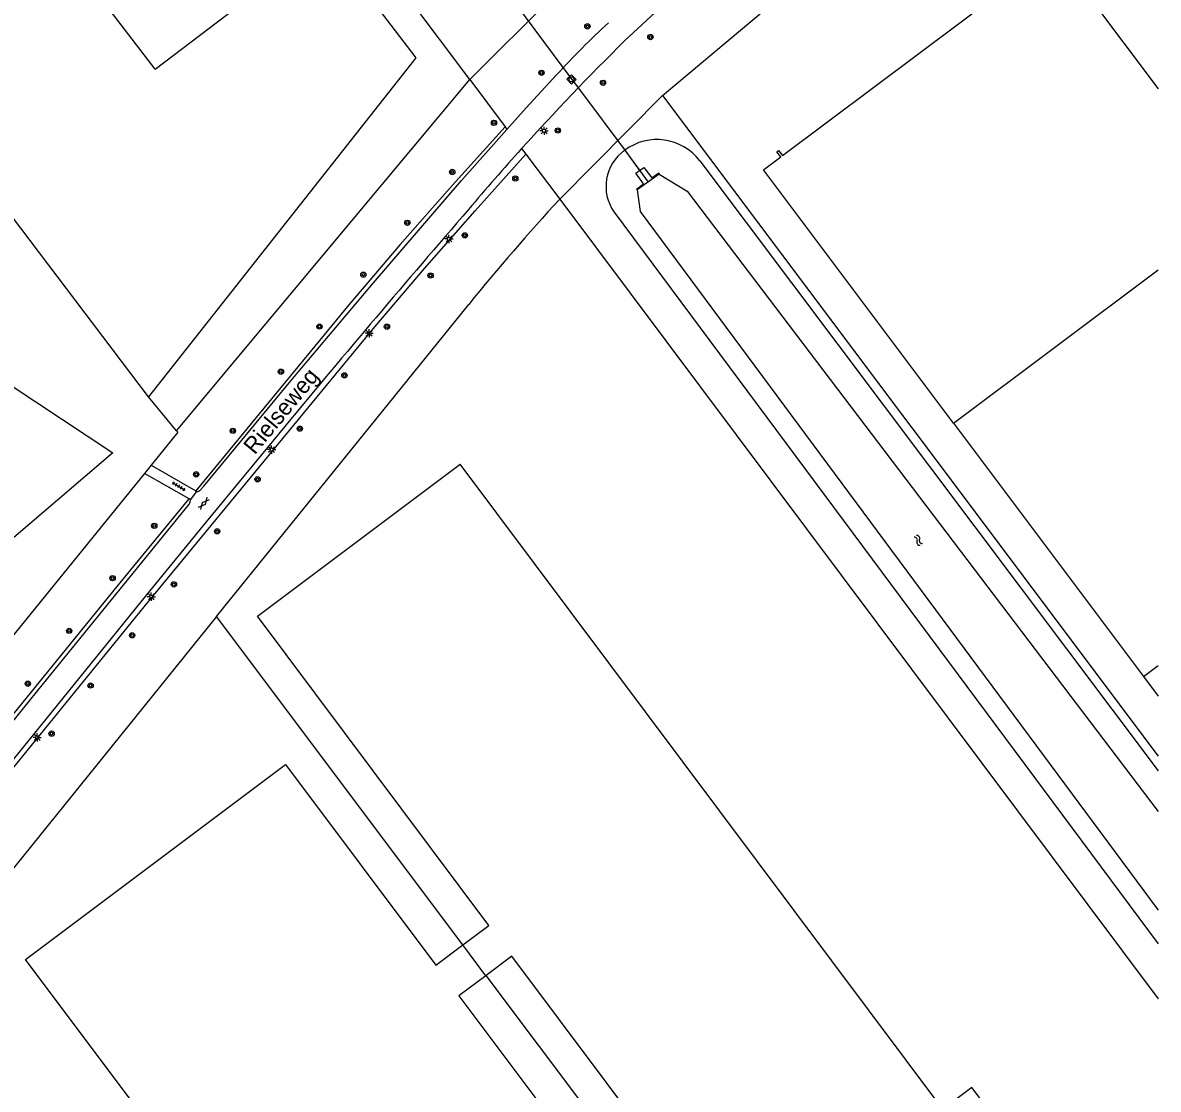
# Model space of a CAD drawing. Extents: x 126000 to 131009, y 393000 to 395500.
# Drawn here: x 130828.7 to 131000, y 394018 to 394178.9 of the extents above; entities that cross this region are included whole.
import ezdxf

# ---------------------------------------------------------------- set-up
doc = ezdxf.new("R2010")
doc.units = 0
for name, color, linetype in [('gg-afsc-hekwerk', 7, 'Continuous'), ('gg-anno-openbare ruimte label', 7, 'Continuous'), ('gg-bbg-bijgebouw', 7, 'Continuous'), ('gg-bbg-hoofdgebouw', 7, 'Continuous'), ('gg-bbg-tussenscheiding', 7, 'Continuous'), ('gg-knt-verharding', 7, 'Continuous'), ('gg-kntw-bovenkant insteek waterloop', 7, 'Continuous'), ('gg-kntw-waterlijn', 7, 'Continuous'), ('gg-kwrk-duiker nz buis', 7, 'Continuous'), ('gg-kwrk-uitstroombak niveau min 01', 7, 'Continuous'), ('gt-grn-groengrens', 7, 'Continuous'), ('gt-symb-boom', 7, 'Continuous'), ('gt-symb-gesloten verharding', 7, 'Continuous'), ('gt-symb-lichtmast', 7, 'Continuous'), ('gt-symb-rioolschacht', 7, 'Continuous'), ('gt-symb-tegel verharding', 7, 'Continuous'), ('gt-symb-watersymbool', 7, 'Continuous')]:
    doc.layers.add(name, color=color, linetype=linetype)

# ---------------------------------------------------------------- blocks, each defined once
blk = doc.blocks.new('gt0-LMAST')
at = {"layer": 'gt-symb-lichtmast'}
for p, q in [((-0.18, 0.17), (-0.45, 0.44)), ((0, 0.25), (0, 0.62)), ((0.17, 0.17), (0.44, 0.44)), ((-0.25, 0), (-0.63, 0)), ((-0.18, -0.18), (-0.45, -0.45)), ((0, -0.25), (0, -0.63)), ((0.44, -0.45), (0.17, -0.18)), ((0.25, 0), (0.62, 0))]:
    blk.add_line(p, q, dxfattribs=at)
blk.add_circle((0, 0), 0.25, dxfattribs=at)
blk = doc.blocks.new('gt0-BOOM')
at = {"layer": 'gt-symb-boom'}
for radius in [0.4, 0.2]:
    blk.add_circle((0, 0), radius, dxfattribs=at)
blk = doc.blocks.new('gt0-RS')
at = {"layer": 'gt-symb-rioolschacht'}
blk.add_lwpolyline([(-0.5, -0.5), (0.5, -0.5), (0.5, 0.5), (-0.5, 0.5)], close=True, dxfattribs=at)
blk.add_circle((0, 0), 0.375, dxfattribs=at)
blk = doc.blocks.new('gt0-GESVH1')
at = {"layer": 'gt-symb-gesloten verharding'}
for p, q in [((-0.99, -0.26), (0.01, 0.24)), ((0.01, -0.26), (-0.99, 0.24)), ((0.01, 0.24), (1.01, -0.26)), ((1.01, 0.24), (0.01, -0.26))]:
    blk.add_line(p, q, dxfattribs=at)
blk = doc.blocks.new('gt0-TEG1')
at = {"layer": 'gt-symb-tegel verharding'}
for p, q in [((-1.12, 0), (1.12, 0)), ((-0.9, -0.25), (-0.9, 0.25)), ((-0.45, -0.25), (-0.45, 0.25)), ((0, -0.25), (0, 0.25)), ((0.45, -0.25), (0.45, 0.25)), ((0.9, -0.25), (0.9, 0.25))]:
    blk.add_line(p, q, dxfattribs=at)
blk = doc.blocks.new('gt0-WA')
at = {"layer": 'gt-symb-watersymbool'}
for centre, start, end in [((-0.32, 0.02), 28.0725, 151.9275), ((0.43, 0.42), 208.0725, 331.9275), ((-0.32, -0.43), 28.0725, 151.9275), ((0.43, -0.03), 208.0725, 331.9275)]:
    blk.add_arc(centre, 0.425, start, end, dxfattribs=at)

msp = doc.modelspace()

# ---------------------------------------------------------------- linework, layer by layer
at = {"layer": 'gg-afsc-hekwerk'}
for p, q in [((130896.14, 394170.36), (130836.65, 394249.39)), ((130925.22, 394167.95), (130956.41, 394194.2)), ((130851.89, 394117.36), (130896.14, 394170.36)), ((130925.22, 394167.95), (131000, 394068.24)), ((130909.69, 394152.32), (131000, 394031.62)), ((130857.9, 394089.3), (130895.96, 394136.42)), ((130851.89, 394117.36), (130847.63, 394122.45)), ((130848.05, 394112.16), (130847.03, 394110.9)), ((130895.07, 394039.76), (130857.9, 394089.3)), ((130925.01, 394000), (130898.6, 394035.15))]:
    msp.add_line(p, q, dxfattribs=at)
for points in [[(130851.89, 394117.36), (130852.09, 394117.12), (130848.05, 394112.16)], [(130847.03, 394110.9), (130795.94, 394047.99), (130783.2, 394063.41), (130773.77, 394075.06), (130769.13, 394081.19)], [(130857.9, 394089.3), (130810.65, 394030.76), (130830.86, 394000)]]:
    msp.add_lwpolyline(points, dxfattribs=at)
msp.add_arc((131157.79, 393924.26), 337, 137.4094, 140.9822, dxfattribs=at)
at = {"layer": 'gg-bbg-bijgebouw'}
msp.add_lwpolyline([(130776.19, 394146.86), (130783.82, 394152.69), (130842.25, 394114.02), (130821.34, 394096.16), (130762.19, 394136.16), (130776.19, 394146.86)], dxfattribs=at)
at = {"layer": 'gg-bbg-hoofdgebouw'}
for p, q in [((130969.11, 394118.48), (130997.77, 394080.27)), ((130997.77, 394080.27), (131000, 394077.29)), ((130895.07, 394039.76), (130899, 394042.7)), ((130898.55, 394035.11), (130898.6, 394035.15))]:
    msp.add_line(p, q, dxfattribs=at)
for points in [[(130848.64, 394171.9), (130839.55, 394183.84), (130855.04, 394195.59), (130832.97, 394225.91), (130834.19, 394226.6), (130829.38, 394234.95), (130829.02, 394234.73), (130829.28, 394234.29)], [(130848.64, 394171.9), (130874.34, 394191.47), (130887.98, 394173.63), (130847.63, 394122.45)], [(130969.11, 394118.48), (130940.43, 394156.72), (130943.03, 394158.67), (130942.44, 394159.45), (130942.72, 394159.66), (130943.31, 394158.89), (130984.42, 394189.72)], [(130847.63, 394122.45), (130824.25, 394153.33), (130824.29, 394153.36)], [(130899, 394042.7), (130864.07, 394089.39), (130894.69, 394112.29)], [(130941.64, 393985.71), (130976.76, 394012.03), (130976.49, 394012.39), (130976.33, 394012.28), (130971.86, 394018.23), (130967.51, 394014.96), (130894.69, 394112.29)], [(130851.82, 394007.23), (130829.08, 394037.57), (130868.32, 394066.99), (130891.01, 394036.71), (130895.07, 394039.76)], [(130941.64, 393985.71), (130930.94, 394000), (130902.48, 394038.04), (130898.6, 394035.15)], [(130898.55, 394035.11), (130894.48, 394032.08), (130933.55, 393979.93), (130894.32, 393950.55), (130871.54, 393980.92)]]:
    msp.add_lwpolyline(points, dxfattribs=at)
at = {"layer": 'gg-bbg-tussenscheiding'}
for p, q in [((130984.42, 394189.72), (131000, 394168.95)), ((130969.11, 394118.48), (131000, 394141.64)), ((130997.77, 394080.27), (131000, 394081.94)), ((130898.55, 394035.11), (130895.07, 394039.76))]:
    msp.add_line(p, q, dxfattribs=at)
at = {"layer": 'gg-knt-verharding'}
for p, q in [((130853.78, 394107.07), (130847.03, 394110.9)), ((130848.05, 394112.16), (130854.77, 394108.28)), ((130853.99, 394106.95), (130853.78, 394107.07)), ((130853.99, 394106.95), (130854.92, 394108.19)), ((130854.77, 394108.28), (130854.92, 394108.19))]:
    msp.add_line(p, q, dxfattribs=at)
for points in [[(130919.48, 394176.18), (130926.1, 394182.4), (130929, 394184.97), (130934.4, 394189.66)], [(130901.73, 394162.84), (130904.61, 394166.1), (130909.21, 394171.06)], [(130855.42, 394108.37), (130856, 394108.98), (130869.39, 394125.2), (130881.61, 394139.7), (130894.88, 394155.11), (130901.73, 394162.84)], [(130868.2, 394118.01), (130856.33, 394103.62), (130847.32, 394092.59), (130822.05, 394061.38), (130813.14, 394050.14), (130810.73, 394046.93), (130810.15, 394045.96), (130810.04, 394046.05), (130802.3, 394036.29)], [(130809.22, 394051.26), (130830.96, 394078.16), (130853.82, 394106.34), (130853.94, 394106.64), (130853.99, 394106.95)]]:
    msp.add_lwpolyline(points, dxfattribs=at)
for centre, radius, start, end in [((130998.44, 394089.88), 120.63, 132.4187, 137.7051), ((131182.33, 393909.24), 374.63, 134.5577, 137.9973), ((131182.79, 393908.87), 375.23, 138.0021, 139.8631), ((132306.35, 392927.97), 1866.67, 139.07619, 140.39306), ((130854.99, 394108.77), 0.591, 263.6002, 317.2102)]:
    msp.add_arc(centre, radius, start, end, dxfattribs=at)
at = {"layer": 'gg-kntw-bovenkant insteek waterloop'}
for p, q in [((130930.82, 394158.09), (131000, 394066.02)), ((130917.89, 394150.35), (131000, 394039.9))]:
    msp.add_line(p, q, dxfattribs=at)
for centre, radius, start, end in [((130924.35, 394153.18), 8.12, 37.2005, 126.7348), ((130923.41, 394154.21), 6.74, 125.6027, 214.9717)]:
    msp.add_arc(centre, radius, start, end, dxfattribs=at)
at = {"layer": 'gg-kntw-waterlijn'}
for points in [[(130924.71, 394156.06), (130928.92, 394153.49), (131000, 394059.87)], [(130921.39, 394153.69), (130921.84, 394150.43), (131000, 394044.98)]]:
    msp.add_lwpolyline(points, dxfattribs=at)
at = {"layer": 'gg-kwrk-duiker nz buis'}
msp.add_line((130910.02, 394172.39), (130913.11, 394168.25), dxfattribs=at)
for points in [[(130899.88, 394185.82), (130903.18, 394181.56), (130910.02, 394172.39)], [(130913.11, 394168.25), (130919.49, 394159.69), (130923.05, 394154.87)]]:
    msp.add_lwpolyline(points, dxfattribs=at)
at = {"layer": 'gg-kwrk-uitstroombak niveau min 01'}
msp.add_line((130924.71, 394156.06), (130921.39, 394153.69), dxfattribs=at)
for points in [[(130921.75, 394156.64), (130922.36, 394157.08), (130923.57, 394155.51), (130924.62, 394156.27), (130924.76, 394156.1), (130924.71, 394156.06)], [(130921.39, 394153.69), (130921.28, 394153.81), (130922.33, 394154.61), (130921.16, 394156.21), (130921.75, 394156.64)]]:
    msp.add_lwpolyline(points, dxfattribs=at)
at = {"layer": 'gt-grn-groengrens'}
for p, q in [((130910.99, 394185.23), (130896.14, 394170.36)), ((130896.14, 394170.36), (130901.46, 394163.2)), ((130909.69, 394152.32), (130925.22, 394167.95)), ((130901.46, 394163.2), (130901.73, 394162.84)), ((130903.93, 394159.93), (130904.58, 394159.08)), ((130904.58, 394159.08), (130909.69, 394152.32)), ((130919.49, 394159.69), (130921.75, 394156.64))]:
    msp.add_line(p, q, dxfattribs=at)
for points in [[(130901.46, 394163.2), (130893.51, 394154.41), (130885.63, 394145.44), (130877.88, 394136.35), (130854.77, 394108.28)], [(130803.96, 394037.97), (130822.09, 394060.19), (130846.98, 394090.76), (130881.78, 394133.04), (130889.29, 394141.85), (130896.91, 394150.55), (130904.58, 394159.08)], [(130793.94, 394043.82), (130795.29, 394042.99), (130795.91, 394042.69), (130796.57, 394042.47), (130797.25, 394042.33), (130797.94, 394042.26), (130798.63, 394042.28), (130799.31, 394042.37), (130799.99, 394042.55), (130800.63, 394042.8), (130801.24, 394043.12), (130801.82, 394043.51), (130802.34, 394043.97), (130802.8, 394044.48), (130843.11, 394094.11), (130853.78, 394107.07)]]:
    msp.add_lwpolyline(points, dxfattribs=at)

# ---------------------------------------------------------------- block references
at = {"layer": 'gt-symb-boom'}
for p in [(130913.87, 394178.38), (130923.37, 394176.77), (130906.94, 394171.38), (130916.22, 394169.87), (130899.77, 394163.83), (130909.41, 394162.67), (130893.47, 394156.41), (130902.99, 394155.42), (130886.7, 394148.74), (130895.37, 394146.84), (130880.06, 394140.91), (130890.21, 394140.79), (130873.44, 394133.08), (130883.62, 394133.05), (130867.62, 394126.26), (130877.2, 394125.72), (130860.37, 394117.34), (130870.47, 394117.67), (130854.83, 394110.76), (130864.1, 394110.02), (130848.52, 394103), (130858.01, 394102.18), (130842.23, 394095.11), (130851.48, 394094.16), (130835.68, 394087.15), (130845.17, 394086.49), (130829.44, 394079.18), (130838.91, 394078.9), (130833.03, 394071.65)]:
    msp.add_blockref('gt0-BOOM', p, dxfattribs=at)
at = {"layer": 'gt-symb-gesloten verharding', "rotation": 49.74681473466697}
msp.add_blockref('gt0-GESVH1', (130855.98, 394106.38), dxfattribs=at)
at = {"layer": 'gt-symb-lichtmast'}
for p in [(130907.33, 394162.62), (130892.98, 394146.3), (130880.94, 394132.06), (130866.21, 394114.51), (130848.07, 394092.3), (130830.85, 394071.08)]:
    msp.add_blockref('gt0-LMAST', p, dxfattribs=at)
at = {"layer": 'gt-symb-rioolschacht', "rotation": -135.97239510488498}
msp.add_blockref('gt0-RS', (130911.47, 394170.38), dxfattribs=at)
at = {"layer": 'gt-symb-tegel verharding', "rotation": -31.20949091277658}
msp.add_blockref('gt0-TEG1', (130852.22, 394108.98), dxfattribs=at)
at = {"layer": 'gt-symb-watersymbool', "rotation": -53.049872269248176}
msp.add_blockref('gt0-WA', (130963.76, 394100.86), dxfattribs=at)

# ---------------------------------------------------------------- texts
at = {"layer": 'gg-anno-openbare ruimte label'}
msp.add_text('Rielseweg', height=2.5, rotation=50.4, dxfattribs=at).set_placement((130863.68, 394113.62))

doc.saveas('drawing.dxf')
